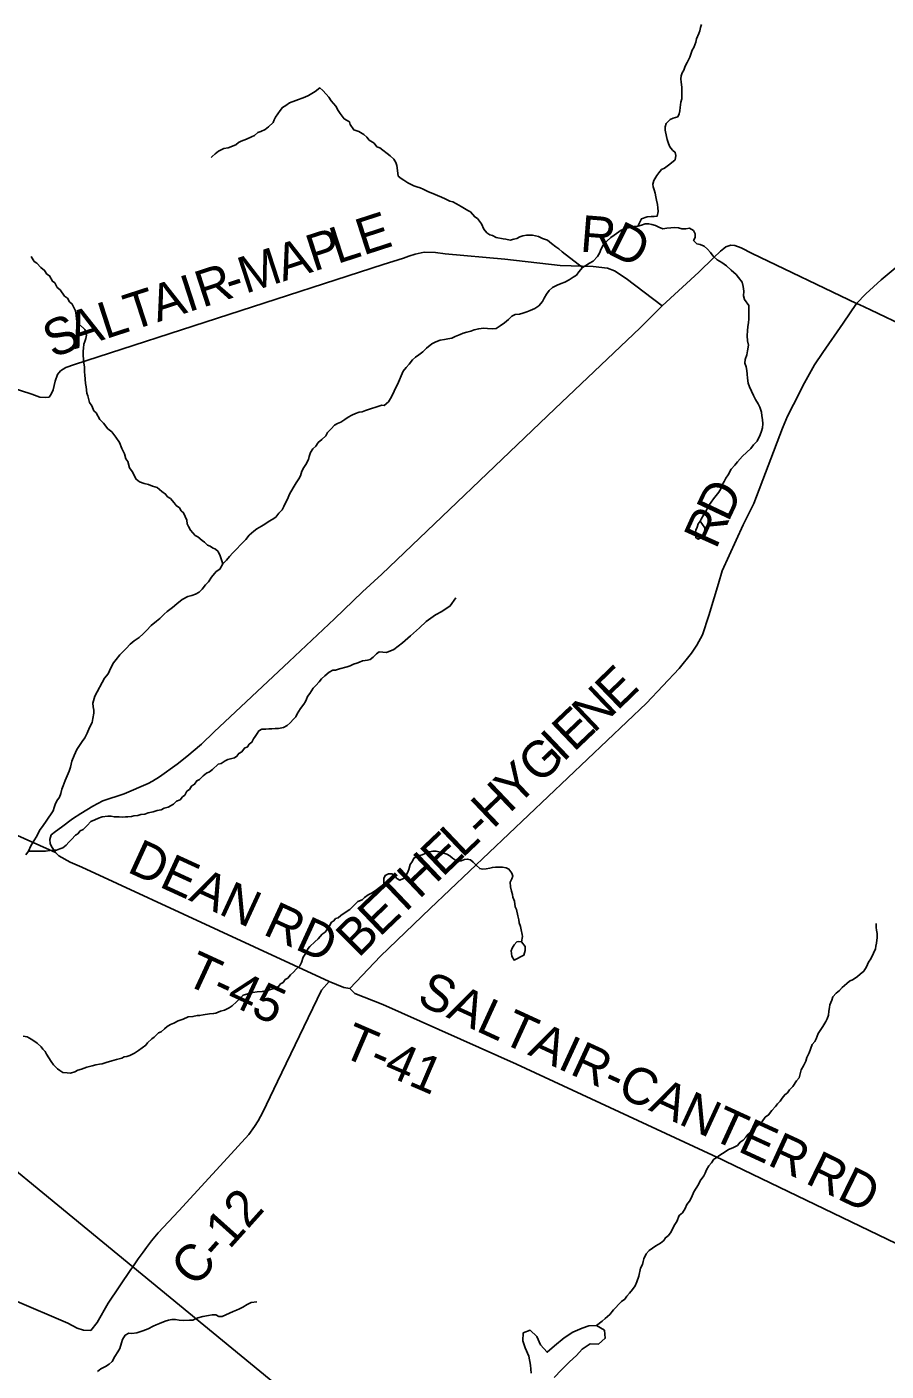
# Model space of a CAD drawing. Extents: x 1310247 to 1664935, y 235267 to 584339.
# Drawn here: x 1503343 to 1510387, y 336394 to 347420 of the extents above; entities that cross this region are included whole.
import ezdxf

# ---------------------------------------------------------------- set-up
doc = ezdxf.new("R2010")
doc.units = 0
for name, color, linetype in [('GM_X_County_Road', 7, 'Continuous'), ('GM_X_County_Road_Text', 7, 'Continuous'), ('GM_X_Minor_Lake', 7, 'Continuous'), ('GM_X_Minor_River', 7, 'Continuous'), ('GM_X_Township', 7, 'Continuous'), ('GM_X_Township_Road', 7, 'Continuous'), ('GM_X_Township_Road_Text', 7, 'Continuous'), ('GM_X_Township_ROW', 7, 'Continuous')]:
    doc.layers.add(name, color=color, linetype=linetype)

msp = doc.modelspace()

# ---------------------------------------------------------------- linework, layer by layer
at = {"layer": 'GM_X_County_Road'}
for points in [[(1504211, 337251), (1504254, 337314), (1504296, 337371), (1504323, 337408), (1504364, 337464), (1504418, 337528), (1504589, 337710), (1504987, 338143), (1505162, 338335), (1505210, 338400), (1505239, 338447), (1505277, 338518), (1505398, 338770), (1505759, 339518), (1505820, 339590), (1505942, 339541), (1505991, 339534), (1506243, 339799), (1506649, 340188), (1508424, 341872), (1508690, 342157), (1508793, 342283), (1508836, 342350), (1508881, 342434), (1508935, 342591), (1508977, 342737), (1509012, 342855), (1509042, 342959), (1509100, 343084), (1509216, 343336), (1509302, 343512), (1509539, 344130), (1509578, 344226), (1509627, 344322), (1509717, 344501), (1509800, 344648), (1509869, 344748), (1510036, 344990), (1510146, 345152), (1510222, 345230), (1510346, 345345), (1510462, 345441)], [(1503243, 336973), (1503678, 336788), (1503755, 336747), (1503808, 336729), (1503866, 336727), (1503920, 336794), (1504008, 336952), (1504195, 337228), (1504210, 337249), (1504211, 337251)]]:
    msp.add_lwpolyline(points, dxfattribs=at)
at = {"layer": 'GM_X_Minor_Lake'}
for points in [[(1508862, 343366), (1508901, 343310), (1508902, 343272), (1508877, 343232), (1508847, 343217), (1508827, 343231), (1508824, 343269), (1508826, 343291)], [(1508826, 343291), (1508839, 343317), (1508847, 343345), (1508862, 343366)], [(1507406, 339960), (1507399, 339916)], [(1507312, 339841), (1507322, 339863), (1507337, 339891), (1507359, 339915), (1507375, 339918), (1507399, 339916)], [(1507399, 339916), (1507429, 339877), (1507428, 339843), (1507416, 339805), (1507337, 339766), (1507319, 339799), (1507312, 339841)], [(1507665, 336342), (1507726, 336405), (1507791, 336470), (1507848, 336523), (1507895, 336575), (1507960, 336618), (1508028, 336615), (1508085, 336664), (1508079, 336730), (1508013, 336768), (1507949, 336767), (1507896, 336747), (1507820, 336715), (1507749, 336668), (1507669, 336603), (1507608, 336549), (1507555, 336611), (1507524, 336677), (1507469, 336730), (1507412, 336707), (1507409, 336643), (1507428, 336585), (1507457, 336518), (1507472, 336443), (1507477, 336377)]]:
    msp.add_lwpolyline(points, dxfattribs=at)
at = {"layer": 'GM_X_Minor_River'}
for points in [[(1508351, 345785), (1508383, 345846), (1508429, 345862), (1508461, 345865), (1508487, 345866), (1508511, 345868), (1508518, 345906), (1508517, 345936), (1508513, 345964), (1508506, 345998), (1508499, 346027), (1508493, 346057), (1508486, 346083), (1508478, 346109), (1508475, 346131), (1508483, 346159), (1508508, 346201), (1508525, 346224), (1508547, 346250), (1508570, 346261), (1508602, 346287), (1508628, 346304), (1508657, 346330), (1508664, 346366), (1508658, 346390), (1508635, 346410), (1508615, 346437), (1508602, 346463), (1508591, 346497), (1508587, 346521), (1508576, 346574), (1508575, 346600), (1508585, 346628), (1508618, 346661), (1508642, 346671), (1508679, 346682), (1508691, 346708), (1508696, 346732), (1508698, 346760), (1508701, 346782), (1508705, 346803), (1508712, 346831), (1508712, 346867), (1508713, 346895), (1508712, 346926), (1508707, 346966), (1508705, 346994), (1508706, 347018), (1508716, 347044), (1508729, 347065), (1508739, 347099), (1508756, 347127), (1508777, 347173), (1508785, 347196), (1508798, 347230), (1508811, 347252), (1508828, 347294), (1508834, 347322), (1508851, 347367), (1508860, 347389), (1508866, 347415), (1508875, 347439)], [(1506320, 346362), (1506236, 346428), (1506212, 346436), (1506189, 346467), (1506149, 346492), (1506129, 346516), (1506105, 346537), (1506064, 346561), (1506022, 346576), (1505992, 346619), (1505987, 346641), (1505943, 346666), (1505912, 346711), (1505896, 346735), (1505877, 346771), (1505837, 346814), (1505818, 346845), (1505796, 346867), (1505768, 346898), (1505745, 346920), (1505706, 346891), (1505651, 346856), (1505621, 346844), (1505548, 346815), (1505497, 346798), (1505467, 346774), (1505438, 346759), (1505420, 346735), (1505401, 346707), (1505380, 346680), (1505370, 346658), (1505362, 346636), (1505323, 346600), (1505296, 346579), (1505262, 346563), (1505237, 346553), (1505209, 346528), (1505185, 346518), (1505142, 346499), (1505099, 346484), (1505077, 346472), (1505055, 346454), (1504994, 346429), (1504956, 346422), (1504915, 346402), (1504887, 346379), (1504862, 346357), (1504853, 346348)], [(1507898, 345446), (1507732, 345574), (1507703, 345600), (1507679, 345617), (1507644, 345644), (1507610, 345672), (1507569, 345685), (1507537, 345702), (1507489, 345711), (1507439, 345712), (1507409, 345705), (1507383, 345697), (1507359, 345684), (1507336, 345678), (1507304, 345671), (1507270, 345678), (1507248, 345682), (1507189, 345693), (1507159, 345708), (1507137, 345714), (1507113, 345731), (1507088, 345761), (1507071, 345804), (1507036, 345849), (1507014, 345861), (1506979, 345902), (1506957, 345914), (1506902, 345948), (1506864, 345968), (1506835, 345985), (1506811, 345992), (1506771, 346010), (1506741, 346023), (1506708, 346036), (1506670, 346053), (1506636, 346067), (1506591, 346088), (1506567, 346101), (1506539, 346109), (1506515, 346116), (1506487, 346131), (1506466, 346141), (1506432, 346162), (1506410, 346176), (1506387, 346197), (1506385, 346219), (1506377, 346283), (1506367, 346307), (1506352, 346334), (1506320, 346362)], [(1506272, 344315), (1506307, 344346), (1506324, 344372), (1506345, 344413), (1506363, 344451), (1506382, 344486), (1506399, 344524), (1506412, 344558), (1506429, 344596), (1506453, 344627), (1506478, 344655), (1506503, 344688), (1506529, 344712), (1506555, 344729), (1506588, 344754), (1506619, 344784), (1506663, 344821), (1506696, 344838), (1506732, 344851), (1506766, 344857), (1506794, 344862), (1506828, 344867), (1506854, 344881), (1506895, 344896), (1506921, 344907), (1506949, 344915), (1506983, 344924), (1507009, 344935), (1507048, 344944), (1507086, 344948), (1507120, 344947), (1507157, 344944), (1507191, 344947), (1507222, 344969), (1507258, 344994), (1507291, 345021), (1507319, 345047), (1507346, 345062), (1507382, 345065), (1507410, 345071), (1507442, 345084), (1507470, 345095), (1507507, 345111), (1507539, 345132), (1507570, 345167), (1507584, 345195), (1507603, 345229), (1507626, 345258), (1507652, 345282), (1507691, 345301), (1507723, 345314), (1507753, 345327), (1507788, 345345), (1507822, 345366), (1507848, 345385), (1507867, 345411), (1507898, 345446), (1507926, 345462), (1507956, 345481), (1507985, 345499), (1508020, 345536), (1508038, 345563), (1508051, 345599), (1508068, 345629), (1508098, 345662), (1508131, 345692), (1508159, 345711), (1508216, 345754), (1508246, 345765), (1508281, 345774), (1508321, 345782), (1508351, 345785), (1508381, 345794), (1508411, 345806), (1508441, 345805), (1508467, 345798), (1508497, 345792), (1508524, 345777), (1508558, 345764), (1508590, 345770), (1508622, 345773), (1508656, 345774), (1508684, 345772), (1508712, 345765), (1508746, 345764), (1508776, 345769), (1508809, 345749), (1508823, 345722), (1508822, 345692), (1508809, 345667), (1508835, 345642), (1508863, 345635), (1508896, 345621), (1508922, 345598), (1508947, 345569), (1508970, 345539), (1509002, 345510), (1509041, 345487), (1509078, 345460), (1509118, 345425), (1509159, 345390)], [(1504948, 343015), (1504926, 343081), (1504912, 343117), (1504888, 343137), (1504864, 343148), (1504844, 343162), (1504824, 343170), (1504799, 343195), (1504779, 343207), (1504743, 343238), (1504723, 343248), (1504703, 343269), (1504684, 343291), (1504668, 343322), (1504657, 343344), (1504653, 343374), (1504628, 343435), (1504608, 343451), (1504595, 343475), (1504567, 343494), (1504549, 343516), (1504520, 343551), (1504496, 343565), (1504480, 343588), (1504450, 343610), (1504411, 343641), (1504373, 343654), (1504341, 343668), (1504305, 343675), (1504265, 343688), (1504239, 343710), (1504206, 343773), (1504184, 343804), (1504169, 343856), (1504154, 343878), (1504144, 343919), (1504121, 343963), (1504102, 344010), (1504072, 344054), (1504039, 344099), (1504007, 344122), (1503970, 344169), (1503940, 344199), (1503911, 344254), (1503892, 344272), (1503876, 344313), (1503857, 344339), (1503841, 344394), (1503834, 344416), (1503829, 344468), (1503823, 344496), (1503818, 344567), (1503815, 344589), (1503814, 344631), (1503810, 344661), (1503803, 344726), (1503804, 344760), (1503806, 344786), (1503809, 344818), (1503817, 344840), (1503826, 344864), (1503830, 344892), (1503819, 344938), (1503774, 344979), (1503754, 344999), (1503750, 345024), (1503747, 345056), (1503740, 345092), (1503714, 345147), (1503691, 345165), (1503675, 345195), (1503651, 345212), (1503616, 345263), (1503592, 345283), (1503573, 345320), (1503553, 345334), (1503528, 345379), (1503506, 345393), (1503488, 345423), (1503457, 345446), (1503425, 345483), (1503401, 345497), (1503377, 345536)], [(1509159, 345390), (1509178, 345364), (1509207, 345325), (1509216, 345291), (1509222, 345253), (1509219, 345213), (1509226, 345185), (1509261, 345134), (1509263, 345066), (1509262, 345024), (1509260, 344996), (1509255, 344960), (1509252, 344930), (1509249, 344886), (1509252, 344845), (1509258, 344809), (1509252, 344763), (1509246, 344731), (1509231, 344692), (1509228, 344662), (1509240, 344633), (1509245, 344601), (1509248, 344573), (1509251, 344539), (1509257, 344499), (1509268, 344467), (1509283, 344432), (1509300, 344398), (1509317, 344365), (1509339, 344329), (1509352, 344300), (1509367, 344260), (1509368, 344230), (1509374, 344200), (1509377, 344164), (1509374, 344132), (1509367, 344104), (1509355, 344074), (1509330, 344022), (1509301, 343991), (1509278, 343961), (1509211, 343899), (1509168, 343852), (1509146, 343826), (1509117, 343793), (1509092, 343745), (1509073, 343718), (1509059, 343690), (1509040, 343658), (1509031, 343632), (1509015, 343605), (1508994, 343577), (1508971, 343548), (1508953, 343522), (1508932, 343492), (1508914, 343457), (1508893, 343421), (1508870, 343382), (1508862, 343366)], [(1504617, 342724), (1504662, 342749), (1504694, 342755), (1504724, 342768), (1504756, 342784), (1504779, 342809), (1504807, 342843), (1504832, 342869), (1504856, 342906), (1504895, 342952), (1504924, 342973), (1504948, 343015), (1504979, 343045), (1505005, 343076), (1505030, 343106), (1505060, 343135), (1505097, 343175), (1505138, 343216), (1505166, 343252), (1505203, 343285), (1505229, 343303), (1505266, 343326), (1505294, 343340), (1505329, 343365), (1505355, 343379), (1505383, 343398), (1505408, 343432), (1505436, 343458), (1505449, 343486), (1505465, 343521), (1505482, 343553), (1505492, 343581), (1505507, 343607), (1505534, 343654), (1505550, 343680), (1505571, 343712), (1505587, 343738), (1505596, 343776), (1505612, 343805), (1505631, 343831), (1505651, 343871), (1505658, 343897), (1505668, 343929), (1505687, 343959), (1505713, 343980), (1505732, 344010), (1505762, 344037), (1505793, 344067), (1505807, 344093), (1505838, 344122), (1505864, 344154), (1505890, 344166), (1505917, 344179), (1505949, 344199), (1505977, 344218), (1506006, 344234), (1506036, 344249), (1506066, 344259), (1506092, 344264), (1506120, 344274), (1506253, 344316), (1506278, 344315)], [(1503333, 340628), (1503356, 340660), (1503374, 340702), (1503399, 340745), (1503424, 340781), (1503446, 340829), (1503477, 340870), (1503502, 340904), (1503516, 340930), (1503543, 340964), (1503559, 340989), (1503566, 341017), (1503574, 341043), (1503589, 341071), (1503611, 341103), (1503622, 341131), (1503630, 341169), (1503639, 341195), (1503657, 341238), (1503674, 341278), (1503689, 341316), (1503699, 341348), (1503710, 341396), (1503731, 341444), (1503752, 341493), (1503768, 341519), (1503797, 341559), (1503819, 341589), (1503836, 341626), (1503857, 341674), (1503878, 341714), (1503884, 341746), (1503891, 341790), (1503891, 341816), (1503886, 341844), (1503884, 341874), (1503901, 341930), (1503978, 342077), (1504010, 342113), (1504031, 342162), (1504052, 342204), (1504074, 342232), (1504105, 342269), (1504156, 342321), (1504189, 342356), (1504223, 342384), (1504264, 342413), (1504296, 342441), (1504323, 342468), (1504361, 342510), (1504406, 342547), (1504432, 342567), (1504467, 342604), (1504493, 342624), (1504536, 342657), (1504571, 342687), (1504617, 342724)], [(1506231, 342295), (1506292, 342289), (1506350, 342314), (1506421, 342367), (1506488, 342426), (1506562, 342491), (1506617, 342542), (1506694, 342597), (1506745, 342624), (1506814, 342671), (1506859, 342736)], [(1506047, 342202), (1506069, 342209), (1506095, 342219), (1506115, 342223), (1506136, 342226), (1506158, 342232), (1506182, 342250), (1506209, 342279), (1506231, 342295)], [(1503356, 340660), (1503494, 340659), (1503531, 340664), (1503557, 340666), (1503585, 340667), (1503613, 340677), (1503636, 340686), (1503664, 340708), (1503687, 340734), (1503707, 340756), (1503740, 340789), (1503760, 340801), (1503779, 340825), (1503803, 340838), (1503838, 340870), (1503867, 340903), (1503901, 340915), (1503931, 340930), (1503960, 340942), (1504006, 340947), (1504034, 340945), (1504058, 340942), (1504098, 340942), (1504127, 340939), (1504151, 340941), (1504171, 340942), (1504199, 340944), (1504219, 340950), (1504251, 340953), (1504278, 340959), (1504310, 340962), (1504336, 340974), (1504378, 340981), (1504411, 340993), (1504443, 340998), (1504467, 341012), (1504500, 341019), (1504544, 341045), (1504569, 341068), (1504599, 341080), (1504618, 341104), (1504638, 341119), (1504655, 341151), (1504675, 341165), (1504692, 341193), (1504718, 341208), (1504735, 341236), (1504757, 341246), (1504788, 341277), (1504816, 341299), (1504839, 341311), (1504865, 341330), (1504912, 341372), (1504936, 341379), (1504969, 341401), (1504989, 341410), (1505011, 341416), (1505044, 341424), (1505064, 341437), (1505079, 341461), (1505105, 341475), (1505126, 341503), (1505152, 341516), (1505166, 341536), (1505187, 341552), (1505201, 341580), (1505214, 341599), (1505230, 341625), (1505243, 341645), (1505269, 341659), (1505301, 341660), (1505327, 341662), (1505352, 341663), (1505378, 341665), (1505406, 341666), (1505446, 341674), (1505477, 341689), (1505501, 341713), (1505528, 341741), (1505548, 341762), (1505559, 341786), (1505586, 341828), (1505613, 341866), (1505627, 341886), (1505635, 341906), (1505644, 341927), (1505662, 341951), (1505675, 341973), (1505689, 341995), (1505712, 342019), (1505740, 342048), (1505759, 342072), (1505786, 342098), (1505820, 342127), (1505851, 342143), (1505873, 342144), (1505907, 342156), (1505968, 342171), (1505994, 342180), (1506020, 342194), (1506047, 342202)], [(1506198, 340333), (1506270, 340388), (1506268, 340412), (1506269, 340436), (1506281, 340460), (1506308, 340472), (1506336, 340473), (1506357, 340459), (1506377, 340436), (1506401, 340420), (1506431, 340435), (1506449, 340457), (1506464, 340482), (1506473, 340510), (1506485, 340550), (1506504, 340578), (1506516, 340602), (1506545, 340617), (1506583, 340630), (1506607, 340640), (1506644, 340653), (1506670, 340659), (1506698, 340658), (1506732, 340651), (1506762, 340643), (1506787, 340634), (1506809, 340622), (1506831, 340603), (1506856, 340584), (1506878, 340576), (1506904, 340579), (1506931, 340591), (1506953, 340594), (1506979, 340588), (1507002, 340569), (1507026, 340545), (1507055, 340516), (1507079, 340512), (1507109, 340515), (1507137, 340520), (1507159, 340526), (1507185, 340529), (1507207, 340529), (1507241, 340528), (1507273, 340522), (1507295, 340511), (1507318, 340479), (1507326, 340454), (1507319, 340432), (1507305, 340405), (1507308, 340367), (1507317, 340330), (1507323, 340304), (1507328, 340282), (1507340, 340248), (1507347, 340203), (1507356, 340181), (1507367, 340129), (1507376, 340096), (1507380, 340070), (1507389, 340040), (1507395, 340014), (1507404, 339976), (1507406, 339960)], [(1505422, 339571), (1505443, 339581), (1505461, 339607), (1505481, 339618), (1505504, 339646), (1505528, 339666), (1505551, 339691), (1505580, 339719), (1505594, 339747), (1505609, 339791), (1505634, 339831), (1505646, 339857), (1505663, 339876), (1505704, 339916), (1505732, 339939), (1505763, 339977), (1505788, 339995), (1505810, 340026), (1505825, 340046), (1505839, 340076), (1505860, 340088), (1505874, 340108), (1505896, 340113), (1505917, 340131), (1505968, 340168), (1505990, 340180), (1506010, 340200), (1506055, 340245), (1506092, 340259), (1506112, 340278), (1506141, 340302), (1506167, 340314), (1506198, 340333)], [(1509371, 338441), (1509396, 338476), (1509424, 338496), (1509451, 338533), (1509480, 338565), (1509496, 338588), (1509520, 338608), (1509535, 338632), (1509556, 338661), (1509578, 338677), (1509596, 338701), (1509623, 338728), (1509654, 338774), (1509675, 338801), (1509692, 338865), (1509709, 338897), (1509728, 338938), (1509738, 338968), (1509757, 339004), (1509782, 339072), (1509803, 339097), (1509815, 339119), (1509822, 339141), (1509830, 339163), (1509847, 339189), (1509870, 339220), (1509892, 339262), (1509903, 339284), (1509914, 339314), (1509918, 339346), (1509923, 339376), (1509927, 339399), (1509942, 339437), (1509951, 339463), (1509979, 339495), (1510004, 339516), (1510028, 339542), (1510065, 339575), (1510088, 339593), (1510116, 339606), (1510152, 339631), (1510175, 339651), (1510205, 339676), (1510226, 339710), (1510243, 339748), (1510262, 339777), (1510285, 339823), (1510301, 339857), (1510304, 339879), (1510308, 339905), (1510313, 339951), (1510314, 339985), (1510309, 340011), (1510307, 340033), (1510306, 340067)], [(1503312, 339141), (1503344, 339137), (1503364, 339126), (1503390, 339110), (1503426, 339083), (1503459, 339054), (1503473, 339034), (1503493, 339015), (1503504, 338993), (1503522, 338965), (1503542, 338934), (1503561, 338906), (1503593, 338873), (1503613, 338859), (1503636, 338844), (1503672, 338840), (1503699, 338839), (1503735, 338849), (1503761, 338862), (1503790, 338872), (1503834, 338887), (1503879, 338898), (1503907, 338906), (1503937, 338911), (1503959, 338915), (1503992, 338925), (1504040, 338940), (1504078, 338951), (1504121, 338962), (1504141, 338972), (1504163, 338976), (1504188, 338983), (1504224, 339003), (1504259, 339024), (1504289, 339046), (1504318, 339068), (1504332, 339087), (1504367, 339119), (1504387, 339133), (1504422, 339168), (1504444, 339178), (1504471, 339202), (1504493, 339221), (1504520, 339237), (1504548, 339249), (1504583, 339268), (1504625, 339281), (1504666, 339299), (1504704, 339302), (1504738, 339310), (1504758, 339311), (1504789, 339317), (1504841, 339324), (1504873, 339327), (1504893, 339331), (1504930, 339346), (1504962, 339356), (1505001, 339375), (1505027, 339391), (1505062, 339423), (1505090, 339450), (1505117, 339478), (1505172, 339495), (1505196, 339501), (1505232, 339504), (1505272, 339507), (1505295, 339513), (1505315, 339517), (1505339, 339524), (1505363, 339530), (1505383, 339536), (1505406, 339549), (1505422, 339571)], [(1508013, 336768), (1508058, 336805), (1508084, 336825), (1508121, 336858), (1508151, 336896), (1508172, 336917), (1508192, 336941), (1508217, 336965), (1508245, 336984), (1508262, 337010), (1508284, 337035), (1508309, 337063), (1508330, 337095), (1508344, 337128), (1508359, 337174), (1508375, 337238), (1508390, 337270), (1508396, 337294), (1508402, 337316), (1508419, 337355), (1508446, 337385), (1508472, 337404), (1508499, 337422), (1508539, 337445), (1508564, 337467), (1508578, 337488), (1508603, 337506), (1508625, 337538), (1508638, 337567), (1508655, 337597), (1508671, 337621), (1508692, 337671), (1508717, 337692), (1508741, 337728), (1508754, 337760), (1508775, 337789), (1508791, 337819), (1508810, 337865), (1508829, 337894), (1508850, 337926), (1508864, 337954), (1508893, 337995), (1508904, 338017), (1508916, 338045), (1508935, 338077), (1508957, 338104), (1508976, 338132), (1509000, 338147), (1509023, 338165), (1509069, 338192), (1509096, 338212), (1509130, 338225), (1509169, 338246), (1509191, 338272), (1509216, 338289), (1509238, 338313), (1509257, 338339), (1509316, 338396), (1509338, 338411), (1509371, 338441)], [(1504590, 336811), (1504624, 336809), (1504676, 336812), (1504702, 336811), (1504743, 336831), (1504785, 336842), (1504833, 336851), (1504861, 336855), (1504891, 336856), (1504917, 336842), (1504945, 336841), (1505034, 336882), (1505060, 336894), (1505086, 336905), (1505112, 336919), (1505149, 336940), (1505181, 336956), (1505227, 336963)], [(1503921, 336391), (1503949, 336413), (1503987, 336432), (1504016, 336452), (1504042, 336474), (1504063, 336515), (1504089, 336553), (1504106, 336581), (1504119, 336625), (1504127, 336653), (1504148, 336688), (1504178, 336706), (1504204, 336704), (1504244, 336709), (1504292, 336724), (1504337, 336741), (1504377, 336763), (1504403, 336774), (1504430, 336784), (1504476, 336803), (1504504, 336811), (1504532, 336818), (1504560, 336818), (1504590, 336811)]]:
    msp.add_lwpolyline(points, dxfattribs=at)
at = {"layer": 'GM_X_Township'}
for points in [[(1533276, 348457), (1532824, 344490), (1532312, 340083), (1532006, 337422), (1531505, 333071), (1531469, 332747), (1531158, 329654), (1530772, 326029), (1528532, 326348), (1524346, 326932), (1524319, 326936), (1516670, 327973), (1515410, 328144), (1515396, 328155), (1510688, 331967), (1508770, 333520), (1507334, 334683), (1504210, 337249), (1502439, 338703), (1501850, 339181), (1500490, 340284), (1499584, 342445), (1499395, 345650), (1499188, 348671)], [(1494192, 337958), (1499473, 342306), (1499584, 342445), (1500490, 340284), (1501850, 339181), (1502439, 338703), (1504210, 337249), (1507334, 334683), (1507086, 333664), (1506297, 330423), (1505134, 325645), (1504652, 323631), (1504598, 323405), (1504587, 323349), (1504578, 323300), (1503185, 317642)]]:
    msp.add_lwpolyline(points, dxfattribs=at)
at = {"layer": 'GM_X_Township_Road'}
for points in [[(1502698, 344630), (1503384, 344407), (1503449, 344382), (1503493, 344380), (1503525, 344384), (1503541, 344408), (1503557, 344443), (1503574, 344513), (1503594, 344568), (1503619, 344598), (1503662, 344626), (1503733, 344650), (1506264, 345470), (1506430, 345524), (1506475, 345539), (1506526, 345557), (1506601, 345572), (1506692, 345569), (1506773, 345559), (1507262, 345514), (1507714, 345463), (1507985, 345455), (1508102, 345442), (1508161, 345418), (1508255, 345355), (1508551, 345131)], [(1508551, 345131), (1508852, 345408), (1508973, 345525), (1509029, 345580), (1509058, 345603)], [(1509058, 345603), (1509074, 345615), (1509113, 345631), (1509148, 345627), (1509200, 345608), (1509288, 345561), (1510146, 345152), (1510167, 345142)], [(1503548, 340693), (1503533, 340722), (1503531, 340754), (1503543, 340792), (1503578, 340821), (1503627, 340857), (1503716, 340925), (1503785, 340969), (1503882, 341028), (1503965, 341071), (1504141, 341130), (1504338, 341215), (1504372, 341232), (1504431, 341269), (1504576, 341373), (1504654, 341435), (1504775, 341536), (1504879, 341638), (1505494, 342215), (1505864, 342565), (1506093, 342785), (1506252, 342931), (1507671, 344286), (1508370, 344953), (1508551, 345131)], [(1510167, 345142), (1510259, 345099), (1510567, 344952), (1510873, 344802), (1511147, 344678), (1511226, 344637)], [(1505820, 339590), (1504917, 340008), (1503794, 340527), (1503697, 340570), (1503604, 340620), (1503577, 340647), (1503550, 340689), (1503548, 340693)], [(1505991, 339534), (1506032, 339492), (1506260, 339401), (1507356, 338913), (1509040, 338130)], [(1509040, 338130), (1509069, 338116), (1510838, 337263)]]:
    msp.add_lwpolyline(points, dxfattribs=at)
at = {"layer": 'GM_X_Township_ROW'}
msp.add_lwpolyline([(1502016, 341362), (1502109, 341326), (1502247, 341262), (1502394, 341175), (1503577, 340647)], dxfattribs=at)

# ---------------------------------------------------------------- texts
at = {"layer": 'GM_X_County_Road_Text'}
for s, rotation, p in [('D', 64.7351, (1509093, 343351)), ('R', 65.709, (1508992, 343128)), ('E', 44.0927, (1508183, 341805)), ('N', 43.5829, (1507990, 341621)), ('E', 43.5756, (1507827, 341467)), ('I', 43.5812, (1507738, 341382)), ('G', 43.5768, (1507546, 341200)), ('Y', 43.5803, (1507355, 341018)), ('H', 43.5754, (1507164, 340836)), ('-', 43.5813, (1507075, 340751)), ('E', 43.5741, (1506750, 340441)), ('L', 43.5787, (1506912, 340596)), ('H', 43.5793, (1506558, 340259)), ('T', 43.5801, (1506396, 340105)), ('E', 43.6968, (1506234, 339950)), ('B', 45.04, (1506061, 339777)), ('C-12', 48.1557, (1504721, 337072))]:
    msp.add_text(s, height=300, rotation=rotation, dxfattribs=at).set_placement(p)
at = {"layer": 'GM_X_Township_Road_Text'}
for s, rotation, p in [('E', 17.9809, (1506100, 345544)), ('L', 17.9809, (1505887, 345474)), ('R', 355.4188, (1507873, 345578)), ('D', 333.518, (1508090, 345567)), ('A', 17.9788, (1505443, 345330)), ('P', 17.9826, (1505694, 345412)), ('M', 17.981, (1505134, 345230)), ('R', 17.9801, (1504782, 345116)), ('A', 17.9817, (1504414, 344996)), ('I', 17.9832, (1504665, 345078)), ('-', 17.9771, (1505016, 345192)), ('T', 17.9776, (1504200, 344927)), ('A', 18.0755, (1503736, 344776)), ('L', 17.983, (1503987, 344858)), ('S', 23.3377, (1503557, 344698)), ('DEAN RD', 335.3117, (1504155, 340493)), ('T-45', 335.1757, (1504622, 339576)), ('SALTAIR-CANTER', 335.3035, (1506529, 339413)), ('T-41', 336.6651, (1505908, 338984)), ('RD', 333.8771, (1509715, 337941))]:
    msp.add_text(s, height=300, rotation=rotation, dxfattribs=at).set_placement(p)

doc.saveas('drawing.dxf')
